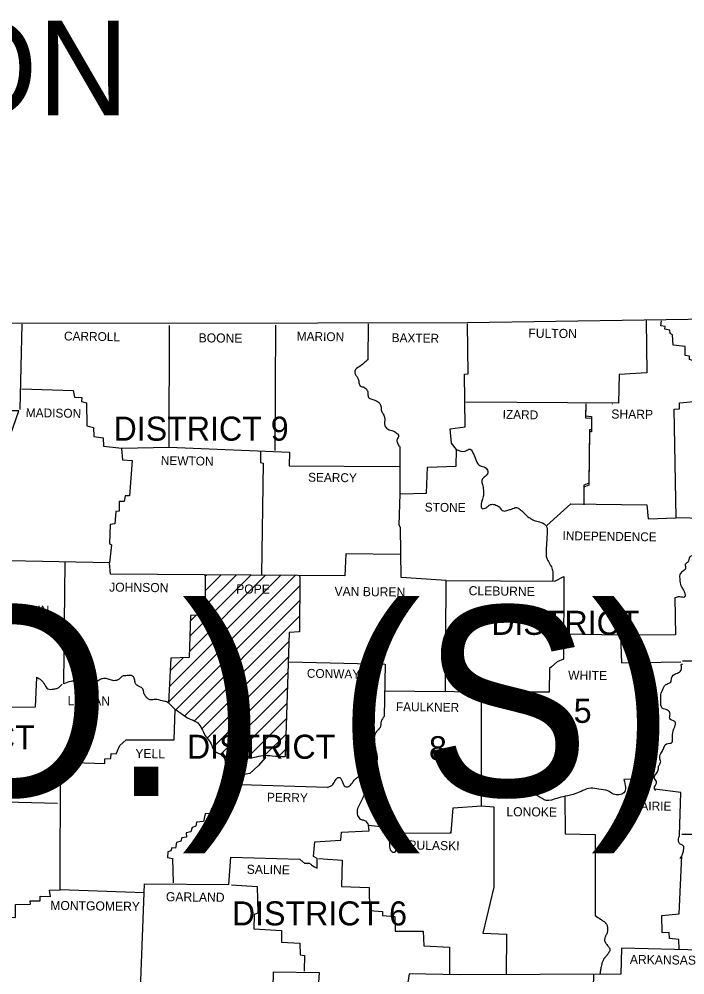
# Model space of a CAD drawing. Extents: x 1373862 to 1376999, y 1168398 to 1170455.
# Drawn here: x 1376253.7 to 1376569.3, y 1169972.5 to 1170425.3 of the extents above; entities that cross this region are included whole.
import ezdxf

# ---------------------------------------------------------------- set-up
doc = ezdxf.new("R2010")
doc.units = 0
doc.layers.add('Level 9', color=7, linetype='Continuous')
doc.layers.add('R_Draft', color=7, linetype='Continuous')

msp = doc.modelspace()

# ---------------------------------------------------------------- linework, layer by layer
at = {"layer": 'Level 9'}
for p, q in [((1376342, 1170161.6), (1376342, 1170162.04)), ((1376386.8, 1170161.1), (1376386.81, 1170161.68))]:
    msp.add_line(p, q, dxfattribs=at)
at = {"layer": 'R_Draft'}
for p, q in [((1376324.58, 1170101.67), (1376384.61, 1170161.69)), ((1376324.95, 1170109.1), (1376377.59, 1170161.75)), ((1376334.49, 1170125.71), (1376370.58, 1170161.81)), ((1376334.7, 1170133), (1376363.56, 1170161.86)), ((1376341.92, 1170147.29), (1376356.55, 1170161.92)), ((1376341.96, 1170154.4), (1376349.54, 1170161.98)), ((1376342, 1170161.51), (1376342.52, 1170162.03)), ((1376328.05, 1170098.06), (1376386.77, 1170156.78)), ((1376332.26, 1170095.2), (1376386.71, 1170149.66)), ((1376334.92, 1170140.3), (1376337.47, 1170142.84)), ((1376336.93, 1170092.81), (1376386.66, 1170142.53)), ((1376386.27, 1170135.08), (1376386.6, 1170135.4)), ((1376340.31, 1170089.11), (1376381.66, 1170130.47)), ((1376325.31, 1170116.53), (1376331.58, 1170122.81)), ((1376342.89, 1170084.62), (1376381.43, 1170123.16)), ((1376568.1, 1170121.3), (1376580, 1170121.3)), ((1376345.43, 1170080.09), (1376381.19, 1170115.85)), ((1376349.25, 1170076.84), (1376380.96, 1170108.54)), ((1376324.57, 1170101.34), (1376324.57, 1170101.34)), ((1376351.55, 1170072.07), (1376380.72, 1170101.24)), ((1376361.86, 1170075.31), (1376380.48, 1170093.93)), ((1376370.11, 1170076.49), (1376380.25, 1170086.62)), ((1376376.81, 1170076.12), (1376380.01, 1170079.32))]:
    msp.add_line(p, q, dxfattribs=at)
for points in [[(1376162.7, 1170281.4), (1376324.4, 1170281.3), (1376466.3, 1170281.6), (1376633.7, 1170284.2), (1376711.3, 1170286)], [(1376255, 1170280.8), (1376254.1, 1170240.3)], [(1376254.8, 1170250.2), (1376279.4, 1170249.4), (1376280, 1170246.2), (1376283.4, 1170246.1), (1376283.3, 1170244.1), (1376285.7, 1170243.5), (1376285.9, 1170232.6), (1376289, 1170231.9), (1376289.2, 1170227.6), (1376293.6, 1170227), (1376293.8, 1170223), (1376302.5, 1170222.1), (1376324.9, 1170222.6), (1376325.1, 1170280.1)], [(1376375.2, 1170280.3), (1376374.9, 1170220.9)], [(1376419.2, 1170281), (1376419, 1170263.9)], [(1376436, 1170039.7), (1376458.5, 1170039.8), (1376459.5, 1170051.6), (1376472.9, 1170052.6), (1376472.9, 1170106.2), (1376455.9, 1170106.7), (1376456.2, 1170159.4), (1376434.8, 1170160.8), (1376434.5, 1170184.4), (1376433.8, 1170185.6), (1376434.4, 1170200.4), (1376446.8, 1170200.8), (1376447.3, 1170213), (1376460.9, 1170213.5), (1376461.1, 1170221.4), (1376458.7, 1170224.5), (1376458.1, 1170231.2), (1376465.1, 1170232.2), (1376464.8, 1170257.1), (1376466.5, 1170257.2), (1376466.3, 1170281)], [(1376551, 1170282.5), (1376551.2, 1170257.7), (1376538.2, 1170257), (1376537.8, 1170243.4), (1376465.5, 1170243.8)], [(1376579.3, 1170120.7), (1376579.8, 1170107.2), (1376606.1, 1170107.9), (1376605.4, 1170188.1), (1376565.1, 1170189), (1376564.2, 1170240.6), (1376566.8, 1170240.7), (1376566.7, 1170243.5), (1376575.2, 1170244.3), (1376574.8, 1170257.4), (1376573.2, 1170257.7), (1376573.3, 1170263.5), (1376571.5, 1170264), (1376571.5, 1170265.7), (1376569.4, 1170266), (1376569.4, 1170270.3), (1376563.7, 1170270.9), (1376563.4, 1170275.7), (1376562.3, 1170276.4), (1376562.1, 1170278), (1376559.8, 1170278.5), (1376559.9, 1170279.7), (1376557.9, 1170280), (1376558.2, 1170282.4)], [(1376522.4, 1170243.1), (1376522.2, 1170237.3), (1376525, 1170237.1), (1376525.1, 1170230.7), (1376524.1, 1170230.7), (1376523.7, 1170205.5), (1376521.4, 1170204.5), (1376521.4, 1170196.1)], [(1376534.9, 1170242.9), (1376535, 1170243)], [(1376297.1, 1170162.4), (1376296.6, 1170167.7), (1376248.9, 1170168.6), (1376248, 1170167.7), (1376242.1, 1170168.2), (1376242.7, 1170179.4), (1376243.9, 1170179.5), (1376245.5, 1170216.6), (1376253.6, 1170239.8), (1376237.5, 1170239.7), (1376236.3, 1170236.7), (1376197.3, 1170238.1), (1376196.7, 1170227.4), (1376189.8, 1170227.4), (1376189.3, 1170220.8), (1376170.6, 1170220.9)], [(1376522.4, 1170242.2), (1376522.2, 1170236.4), (1376525, 1170236.2), (1376525.1, 1170229.8), (1376524.1, 1170229.8), (1376523.7, 1170204.6), (1376521.4, 1170203.6), (1376521.4, 1170195.2)], [(1376302.3, 1170221.9), (1376302.7, 1170216.5), (1376307.3, 1170216.2), (1376306.1, 1170199.4), (1376304, 1170199.5), (1376303.6, 1170196.8), (1376301.2, 1170196.8), (1376301.1, 1170192.2), (1376299.6, 1170192.1), (1376299.1, 1170186.2), (1376296.9, 1170185.9), (1376296.6, 1170176.9), (1376297.6, 1170176.2), (1376296.6, 1170167.7)], [(1376324.9, 1170222.6), (1376381.9, 1170220.2), (1376381.8, 1170213.7), (1376434.1, 1170213.3)], [(1376368.2, 1170220.5), (1376368.1, 1170215.3), (1376369.4, 1170215), (1376368.6, 1170162.2)], [(1376434.4, 1170200.4), (1376434.3, 1170222.9)], [(1376503.8, 1170185.4), (1376515.2, 1170195.7), (1376551.2, 1170195.2), (1376551.9, 1170188.5), (1376565, 1170189)], [(1376434.4, 1170171.7), (1376408.6, 1170172), (1376408.1, 1170161.5), (1376297.1, 1170162.4)], [(1376274.9, 1170110.4), (1376275.6, 1170168.1)], [(1376342, 1170161.6), (1376341.9, 1170142.9), (1376335, 1170142.8), (1376334.4, 1170122.9), (1376325.6, 1170122.6), (1376324.57, 1170101.34)], [(1376386.8, 1170161.1), (1376386.6, 1170135.1), (1376381.8, 1170134.7), (1376379.9, 1170075.9)], [(1376456.2, 1170159.4), (1376507.6, 1170159.1), (1376512, 1170161.2), (1376511.7, 1170122.1), (1376508.7, 1170120.8), (1376506, 1170118.5), (1376505.1, 1170117.6), (1376505, 1170106.4), (1376472.3, 1170106.4)], [(1376564.6, 1170151.2), (1376564.8, 1170133.6), (1376538.8, 1170133.5), (1376512.1, 1170134)], [(1376538.8, 1170133.5), (1376539.2, 1170120.4), (1376567.3, 1170120.9)], [(1376381.6, 1170120.8), (1376427.3, 1170119.7), (1376426.7, 1170095)], [(1376568.1, 1170119.6), (1376567.6, 1170119.5)], [(1376262, 1170113.6), (1376261.3, 1170099.3), (1376248.3, 1170099.2), (1376247.6, 1170086.2), (1376234.7, 1170086.5), (1376234.3, 1170073.1), (1376220.8, 1170073), (1376220.4, 1170059.6), (1376228.9, 1170059.1), (1376228.6, 1170055), (1376272, 1170053.8)], [(1376426.8, 1170107.1), (1376455.9, 1170106.7)], [(1376606.1, 1170107.9), (1376607.6, 1170053.1), (1376583.8, 1170053), (1376583.7, 1170050.8), (1376576.8, 1170050.4), (1376576.2, 1170039), (1376567.8, 1170039)], [(1376244.1, 1169951.1), (1376245.2, 1170000.3), (1376252, 1169999.7), (1376252.1, 1170005.8), (1376259.1, 1170006), (1376259, 1170007.6), (1376263.7, 1170007.6), (1376263.8, 1170009.8), (1376268.6, 1170009.7), (1376268.2, 1170012.7), (1376273.2, 1170012.8), (1376273.4, 1170071.3), (1376279.4, 1170071.5), (1376279.9, 1170073.1), (1376294.4, 1170072.7), (1376294.3, 1170074.8), (1376297.2, 1170075.1), (1376297.3, 1170077.4), (1376299.8, 1170077.2), (1376301.5, 1170081.2), (1376304.5, 1170083.8), (1376327.3, 1170083.9), (1376327.7, 1170098.3)], [(1376370.6, 1170075.5), (1376367, 1170071.6), (1376363.1, 1170067.9), (1376358.6, 1170067.2), (1376358.6, 1170062.5), (1376356.4, 1170062.2), (1376356, 1170059.8), (1376353.5, 1170059.6), (1376353.3, 1170058.5), (1376351.6, 1170058.4), (1376351.5, 1170056.3), (1376349.1, 1170056.2), (1376348.9, 1170053.8), (1376346.9, 1170053.8), (1376347, 1170051), (1376344.8, 1170051.2), (1376344.7, 1170049), (1376342, 1170048.8), (1376341.2, 1170045.2), (1376337.8, 1170044.9), (1376337.5, 1170042.9), (1376335.7, 1170042.4), (1376335.2, 1170040.3), (1376332.9, 1170039.8), (1376333.1, 1170037.7), (1376330.8, 1170037.5), (1376330.4, 1170035.9), (1376328.3, 1170035.3), (1376327.8, 1170032.6), (1376326.2, 1170032.7), (1376325.7, 1170031.3), (1376324.2, 1170030.8), (1376324.1, 1170028.1), (1376326.4, 1170027.7), (1376326.8, 1170016.1)], [(1376399.9, 1170061.3), (1376358.7, 1170062.6)], [(1376554.9, 1170065.7), (1376540.4, 1170065)], [(1376566.7, 1170038.5), (1376567.4, 1170058.9), (1376554.9, 1170060.5)], [(1376512.4, 1170057.08), (1376512.6, 1170039.3), (1376526.7, 1170039), (1376526.8, 1170000.6)], [(1376472.9, 1170052.6), (1376478.7, 1170052.2), (1376478.8, 1170014), (1376473.6, 1169992.3), (1376484.7, 1169991.8), (1376484.6, 1169972.69)], [(1376395, 1170023.1), (1376395, 1170027.7), (1376393.2, 1170028.6), (1376393.9, 1170035.6), (1376406.2, 1170036.3), (1376406.6, 1170040.2), (1376419.7, 1170040.7), (1376419.4, 1170043.4), (1376426.6, 1170042.6)], [(1376458, 1170039.9), (1376458.5, 1170040.4)], [(1376313, 1170011.3), (1376313.2, 1170015.6), (1376353.2, 1170015.4), (1376354.1, 1170028.3), (1376386.8, 1170027.3)], [(1376395.7, 1170027.6), (1376406.9, 1170026.9), (1376406.5, 1170014.4), (1376419.6, 1170013.9), (1376419.8, 1170003), (1376426, 1170002.5), (1376426, 1170000.6), (1376431.8, 1170000.2), (1376432, 1169993.2), (1376445.2, 1169993.2), (1376445.6, 1169986.3), (1376457.8, 1169985.7), (1376457.7, 1169972.7)], [(1376566.65, 1169984.48), (1376566.5, 1169989.3), (1376562, 1169989.8), (1376561.9, 1169992.6), (1376558.6, 1169992.5), (1376558.4, 1170000.6), (1376566.6, 1170001.5), (1376567.8, 1170028.9)], [(1376313, 1170011.3), (1376273.2, 1170012.8)], [(1376354.4, 1170015.2), (1376366.5, 1170014.3), (1376366.9, 1170001.7), (1376365.2, 1170001.1), (1376365, 1169994.4), (1376378.1, 1169993.5), (1376378.1, 1169988), (1376386.8, 1169987.5), (1376386.9, 1169982), (1376389, 1169981.7), (1376388.9, 1169974.3)], [(1376310.7, 1169949), (1376313, 1170011.3)], [(1376577, 1169984.2), (1376539.2, 1169985.2), (1376539, 1169972.9), (1376462.5, 1169972.6)], [(1376311.4, 1169957.3), (1376368.6, 1169956.5), (1376369.7, 1169966), (1376374.2, 1169966), (1376374.3, 1169974), (1376395.9, 1169973.7), (1376395.7, 1169968.9), (1376401.3, 1169968.5), (1376401.3, 1169959.7), (1376404.9, 1169959.4)], [(1376462.5, 1169972.6), (1376438.6, 1169973), (1376437.7, 1169966.9), (1376414.4, 1169966.2), (1376414.2, 1169964.2), (1376410.9, 1169963.6), (1376410.5, 1169960.2), (1376404.9, 1169959.4)], [(1376525.93, 1169972.85), (1376525.1, 1169933.6), (1376539, 1169932.5)]]:
    msp.add_lwpolyline(points, dxfattribs=at)
for points in [[(1376419, 1170263.9), (1376417.2, 1170262.4), (1376415.6, 1170261), (1376413.2, 1170259.3), (1376412.9, 1170257.7), (1376413.7, 1170256.1), (1376414.5, 1170254.8), (1376414.8, 1170253), (1376415.5, 1170251.5), (1376417.2, 1170250.9), (1376418.6, 1170249.6), (1376419.1, 1170247.8), (1376419.3, 1170246.1), (1376420.9, 1170245.3), (1376422.7, 1170244.7), (1376424.4, 1170243.5), (1376425.2, 1170242), (1376425.4, 1170240.1), (1376426.1, 1170238.6), (1376426.9, 1170236.8), (1376427.1, 1170235.3), (1376426.9, 1170233.8), (1376427.3, 1170232.4), (1376428.6, 1170231), (1376430.9, 1170230.3), (1376432.5, 1170229.3), (1376433.6, 1170227.9), (1376432.9, 1170226.2), (1376433, 1170224.7), (1376433.9, 1170222.9)], [(1376461.1, 1170221.4), (1376465.1, 1170220.7), (1376467.5, 1170221.6), (1376469.2, 1170219), (1376470.1, 1170217), (1376471.6, 1170214.1), (1376474, 1170213.2), (1376475.8, 1170211.6), (1376475.8, 1170209.9), (1376474.2, 1170208.3), (1376473, 1170206.7), (1376473.4, 1170204.8), (1376473.8, 1170202.2), (1376473.8, 1170199.7), (1376473.2, 1170197.4), (1376472.7, 1170195.3), (1376473.2, 1170193.5), (1376475.1, 1170193.8), (1376477.1, 1170195.3), (1376479.2, 1170195.3), (1376481.2, 1170194.2), (1376483.3, 1170192.3), (1376485.4, 1170192.7), (1376487.1, 1170193.2), (1376489.5, 1170193.9), (1376491.2, 1170193), (1376492.7, 1170191.8), (1376494.5, 1170189.9), (1376496.2, 1170188.7), (1376498.4, 1170187.6), (1376501.1, 1170186.9), (1376503.6, 1170185.2), (1376504, 1170182.3), (1376503.9, 1170179.8), (1376503.7, 1170176.7), (1376503.5, 1170173.3), (1376503.8, 1170170), (1376504.9, 1170167.8), (1376506.3, 1170165.2), (1376506.7, 1170162.8), (1376506.6, 1170159)], [(1376582.5, 1170187.2), (1376581.3, 1170184.1), (1376579.9, 1170181.1), (1376579, 1170178.5), (1376577.1, 1170177), (1376576.5, 1170175.6), (1376574.8, 1170175), (1376573.5, 1170173), (1376572.9, 1170171.2), (1376571.5, 1170170.4), (1376570.8, 1170168.2), (1376569.5, 1170167), (1376569.6, 1170165), (1376568.1, 1170163.6), (1376566.9, 1170162), (1376566.9, 1170159.8), (1376567.4, 1170156.9), (1376568.4, 1170155.2), (1376569.3, 1170153), (1376569.2, 1170151.6), (1376566.7, 1170151.6), (1376564.6, 1170151.2)], [(1376555.4, 1170059.8), (1376554.9, 1170060.5), (1376555.5, 1170062.7), (1376555.8, 1170064.1), (1376554.8, 1170066.1), (1376555.7, 1170067.8), (1376556.7, 1170069.6), (1376557, 1170071.7), (1376557.8, 1170073.1), (1376557.5, 1170074.9), (1376557.9, 1170077.4), (1376559, 1170079.3), (1376560.6, 1170082), (1376563.3, 1170082.7), (1376563.5, 1170083.8), (1376563.4, 1170086.3), (1376564.5, 1170090), (1376564.9, 1170091.3), (1376564.5, 1170092.5), (1376562.1, 1170093.9), (1376562.3, 1170096), (1376561.1, 1170098), (1376558.6, 1170098.9), (1376557.9, 1170102.3), (1376557.9, 1170105.3), (1376559, 1170108.2), (1376560.7, 1170110.3), (1376562.5, 1170111.1), (1376563, 1170113.1), (1376565.2, 1170115.3), (1376567.1, 1170116.2), (1376567.6, 1170119.5)], [(1376262, 1170113.6), (1376264.2, 1170112.2), (1376265.9, 1170109.9), (1376267.4, 1170108), (1376269.9, 1170107.9), (1376271.9, 1170108.3), (1376274.2, 1170110.3)], [(1376327.7, 1170098.3), (1376325.8, 1170100.1), (1376323.8, 1170101.8), (1376321.6, 1170102.3), (1376318.2, 1170103), (1376316, 1170102.8), (1376314.7, 1170103.4), (1376313.8, 1170104.4), (1376312.9, 1170105.9), (1376312.4, 1170108), (1376310.7, 1170109.1), (1376308.8, 1170110.8), (1376308.5, 1170112.6), (1376307, 1170114.3), (1376304.9, 1170114.3), (1376302.5, 1170113.9), (1376301.1, 1170112.6), (1376298.7, 1170111.9), (1376296.5, 1170112.5), (1376294.4, 1170112.9), (1376292.2, 1170112.5), (1376290.2, 1170111.2), (1376288.2, 1170110.5), (1376285.5, 1170110.3), (1376283, 1170111.3), (1376280.6, 1170111.7), (1376278.2, 1170111.5), (1376274.9, 1170110.4)], [(1376327.7, 1170098.3), (1376331.2, 1170095.9), (1376334.5, 1170093.8), (1376337.9, 1170092.3), (1376339.8, 1170090.1), (1376341.5, 1170086.7), (1376342.9, 1170084.6), (1376344.7, 1170082), (1376346, 1170079.1), (1376348.1, 1170077.5), (1376350.3, 1170076.1), (1376351.4, 1170073.6), (1376351.9, 1170071.1), (1376354.3, 1170069.9), (1376356.6, 1170070.4), (1376357.9, 1170071.9), (1376359.1, 1170074.5), (1376361.8, 1170075.3), (1376365.3, 1170075.6), (1376369.3, 1170076.5), (1376373.7, 1170076.3), (1376379.9, 1170075.9)], [(1376426.7, 1170095), (1376425.4, 1170092.7), (1376424.8, 1170089.7), (1376423.2, 1170087.8), (1376422.2, 1170085.6), (1376422.1, 1170082.7), (1376422.6, 1170080.1), (1376423.1, 1170077.6), (1376423.5, 1170075.3), (1376423, 1170072.4), (1376421.7, 1170069.9), (1376419.7, 1170069.2), (1376417.8, 1170067.5)], [(1376399.9, 1170061.3), (1376402.4, 1170062.7), (1376403.7, 1170064.8), (1376405.3, 1170066.1), (1376406.9, 1170064.3), (1376408.3, 1170061.7), (1376409.8, 1170061.7), (1376411.7, 1170063.5), (1376412.9, 1170065.1), (1376414.4, 1170066.3), (1376416, 1170066.8), (1376417.7, 1170067), (1376419, 1170065.1), (1376418.6, 1170062.1), (1376418.6, 1170060.1), (1376417.5, 1170058), (1376416.3, 1170055.8), (1376415, 1170053.3), (1376414, 1170050.6), (1376414.2, 1170048), (1376415.6, 1170046.3), (1376417.2, 1170045.8), (1376419.4, 1170043.6)], [(1376540.4, 1170065), (1376540.4, 1170058.8), (1376535.5, 1170058.1), (1376532.8, 1170059.7), (1376528.5, 1170060.5), (1376524.7, 1170061), (1376520.9, 1170059.8), (1376517.6, 1170058.4), (1376512.5, 1170057.1), (1376508.6, 1170056.1), (1376503.6, 1170055.2), (1376499.7, 1170057.2), (1376496.4, 1170058.5), (1376491.7, 1170059.1), (1376487.7, 1170060.4), (1376484.2, 1170061.4), (1376478.7, 1170061.2), (1376472.9, 1170060.99)], [(1376426.6, 1170042.6), (1376428.3, 1170040.4), (1376429.3, 1170037.4), (1376429.3, 1170034), (1376430.1, 1170031.2), (1376431.7, 1170030.6), (1376432.7, 1170033), (1376432.5, 1170035.4), (1376432.5, 1170036.8), (1376434.2, 1170038), (1376436, 1170039.7)], [(1376566.9, 1170027.7), (1376567.8, 1170028.9), (1376568.2, 1170029.7), (1376568.7, 1170031.7), (1376568.5, 1170033.7), (1376567.1, 1170034.4), (1376566.3, 1170036.5), (1376566.7, 1170038.5)], [(1376386.8, 1170027.3), (1376388, 1170026.2), (1376389.3, 1170025.4), (1376390.9, 1170025.5), (1376392.4, 1170024.6), (1376395, 1170023.1)], [(1376526.8, 1170000.6), (1376529.3, 1169998.9), (1376529.97, 1169998.46), (1376530.63, 1169998.01), (1376531.28, 1169997.52), (1376531.59, 1169997.23), (1376531.75, 1169997.07), (1376531.9, 1169996.9), (1376532.3, 1169996.28), (1376532.5, 1169995.6), (1376532.58, 1169994.9), (1376532.59, 1169994.55), (1376532.6, 1169994.2), (1376532.6, 1169993.73), (1376532.57, 1169993.25), (1376532.51, 1169992.77), (1376532.4, 1169992.3), (1376532.23, 1169991.89), (1376532.01, 1169991.49), (1376531.78, 1169991.11), (1376531.6, 1169990.7), (1376531.4, 1169990.08), (1376531.24, 1169989.43), (1376531.4, 1169988.2), (1376531.54, 1169987.97), (1376531.68, 1169987.74), (1376531.98, 1169987.29), (1376532.6, 1169986.4), (1376532.88, 1169986.03), (1376533.18, 1169985.65), (1376533.59, 1169985.09), (1376533.65, 1169985), (1376533.7, 1169984.9), (1376533.79, 1169984.26), (1376533.52, 1169983.57), (1376533.06, 1169982.87), (1376532.82, 1169982.53), (1376532.6, 1169982.2), (1376532.37, 1169981.87), (1376532.12, 1169981.56), (1376531.61, 1169980.97), (1376531.12, 1169980.37), (1376530.89, 1169980.04), (1376530.7, 1169979.7), (1376530.38, 1169979.02), (1376530.1, 1169978.33), (1376529.7, 1169976.9), (1376529.52, 1169975.89), (1376529.34, 1169974.89), (1376529.02, 1169972.86)]]:
    msp.add_spline(points, degree=3, dxfattribs=at)

# ---------------------------------------------------------------- texts
for s, height, p in [('ARKANSAS DEPARTMENT OF TRANSPORTATION ', 45, (1374874.9, 1170379.67)), ('DISTRICT 9', 11.4, (1376298.5, 1170225.6)), ('STRS. & APPRS. (POPE CO.) (S)', 90, (1374732.37, 1170057.19)), ('DISTRICT', 11.4, (1376477.5, 1170133.6)), ('5', 11.4, (1376516.6, 1170091.9)), ('DISTRICT', 11.4, (1376190.9, 1170079.4)), ('DISTRICT', 11.4, (1376333.3, 1170074.9)), ('8', 11.4, (1376448, 1170074.2)), ('DISTRICT 6', 11.4, (1376354.59, 1169995.94))]:
    msp.add_text(s, height=height, dxfattribs=at).set_placement(p)
for s, height, rotation, p in [('CARROLL', 4.201, 359.1481, (1376275, 1170273.1)), ('BOONE', 4.301, 359.4001, (1376338.8, 1170272.2)), ('MARION', 4.201, 359.1854, (1376385.3, 1170273)), ('BAXTER', 4.201, 359.2559, (1376430.3, 1170272.3)), ('FULTON', 4.3, 359.4996, (1376495.1, 1170274.4)), ('MADISON', 4.201, 359.0906, (1376256.9, 1170236.8)), ('IZARD', 4.199, 358.9258, (1376482.9, 1170236)), ('SHARP', 4.3, 359.3905, (1376534.4, 1170236.1)), ('NEWTON', 4.201, 359.2717, (1376320.9, 1170214.1)), ('SEARCY', 4.199, 359.2527, (1376390.7, 1170206.2)), ('STONE', 4.199, 359.4001, (1376446, 1170192)), ('INDEPENDENCE', 4.1994, 359.2187, (1376511.3, 1170178.5)), ('JOHNSON', 4.301, 359.3514, (1376296.4, 1170154.1)), ('POPE', 4.301, 359.6155, (1376356.6, 1170153.2)), ('VAN BUREN', 4.301, 359.3508, (1376403.2, 1170152.1)), ('CLEBURNE', 4.3, 359.2535, (1376466.8, 1170152.4)), ('FRANKLIN', 4.301, 359.1815, (1376239.6, 1170143.5)), ('CONWAY', 4.199, 359.0371, (1376390.1, 1170113.3)), ('WHITE', 4.301, 359.3139, (1376513.9, 1170112.4)), ('LOGAN', 4.301, 359.3969, (1376276.7, 1170100.3)), ('FAULKNER', 4.201, 359.2486, (1376432.3, 1170097.5)), ('YELL', 4.301, 359.1987, (1376308.8, 1170075.3)), ('PERRY', 4.201, 359.0858, (1376371.2, 1170054.6)), ('PRAIRIE', 4.201, 359.2116, (1376540.4, 1170050.6)), ('LONOKE', 4.301, 359.4974, (1376484.7, 1170047.7)), ('PULASKI', 4.301, 359.053, (1376438.2, 1170031.9)), ('SALINE', 4.301, 359.1491, (1376361.6, 1170020.4)), ('MONTGOMERY', 4.301, 359.2944, (1376268.5, 1170003.3)), ('GARLAND', 4.301, 359.3658, (1376323.3, 1170007.4)), ('ARKANSAS', 4.3, 359.2678, (1376543.2, 1169977.7))]:
    msp.add_text(s, height=height, rotation=rotation, dxfattribs=at).set_placement(p)

doc.saveas('drawing.dxf')
